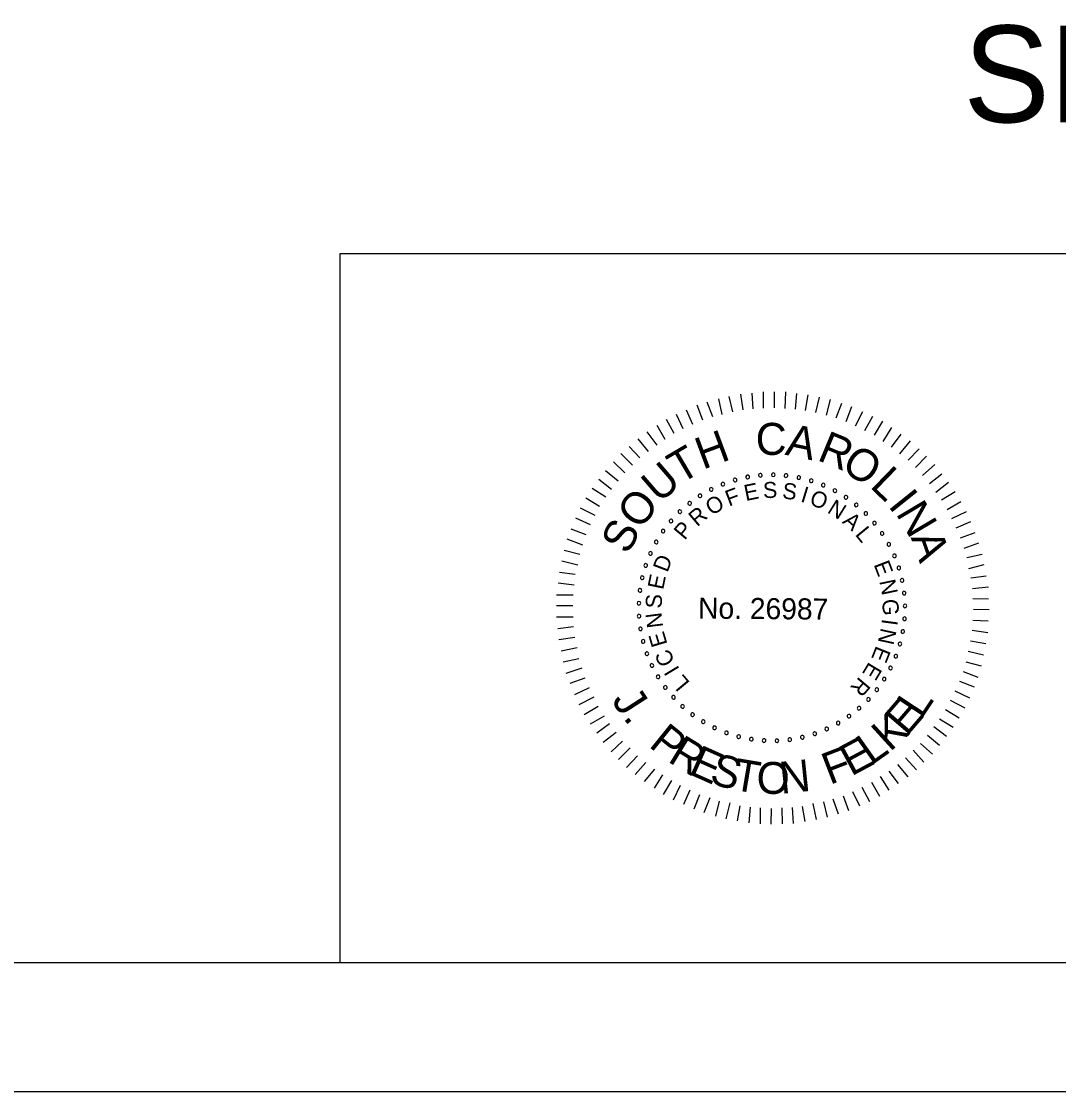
# Model space of a CAD drawing. Extents: x 1970675.2 to 1970711.3, y 796145.2 to 796167.2.
# Drawn here: x 1970696.635 to 1970700.655, y 796145.246 to 796149.396 of the extents above; entities that cross this region are included whole.
import ezdxf

# ---------------------------------------------------------------- set-up
doc = ezdxf.new("R2010")
doc.units = 0
for name, color, linetype in [('BR_BORDER LINES', 7, 'Continuous'), ('BR_TEXT', 7, 'Continuous'), ('Level 31', 7, 'Continuous')]:
    doc.layers.add(name, color=color, linetype=linetype)

msp = doc.modelspace()

# ---------------------------------------------------------------- linework, layer by layer
at = {"layer": 'BR_BORDER LINES'}
for p, q in [((1970697.8703, 796148.4964), (1970703.2355, 796148.4964)), ((1970697.8703, 796145.7463), (1970697.8703, 796148.4964)), ((1970677.0698, 796145.7463), (1970710.7358, 796145.7463))]:
    msp.add_line(p, q, dxfattribs=at)
at = {"layer": 'BR_TEXT'}
for p, q in [((1970699.3925, 796147.882), (1970699.3784, 796147.9414)), ((1970699.432, 796147.8895), (1970699.4231, 796147.9504)), ((1970699.4715, 796147.8934), (1970699.4677, 796147.9544)), ((1970699.511, 796147.8957), (1970699.5116, 796147.96)), ((1970699.5531, 796147.8979), (1970699.5536, 796147.9597)), ((1970699.5951, 796147.895), (1970699.5974, 796147.9593)), ((1970699.6354, 796147.8921), (1970699.6402, 796147.9529)), ((1970699.674, 796147.8875), (1970699.6848, 796147.9483)), ((1970699.7143, 796147.8794), (1970699.7285, 796147.9385)), ((1970699.2755, 796147.8495), (1970699.2545, 796147.9081)), ((1970699.3151, 796147.8621), (1970699.2932, 796147.9198)), ((1970699.3512, 796147.8721), (1970699.338, 796147.9331)), ((1970699.7554, 796147.8688), (1970699.7713, 796147.9295)), ((1970699.7922, 796147.8582), (1970699.8141, 796147.9155)), ((1970699.8316, 796147.8449), (1970699.8535, 796147.9031)), ((1970699.1997, 796147.8158), (1970699.1735, 796147.8718)), ((1970699.2368, 796147.8327), (1970699.2132, 796147.8887)), ((1970699.8675, 796147.8275), (1970699.8954, 796147.883)), ((1970699.9034, 796147.81), (1970699.9347, 796147.8656)), ((1970699.1299, 796147.7744), (1970699.0994, 796147.8287)), ((1970699.1652, 796147.7981), (1970699.1348, 796147.8524)), ((1970699.941, 796147.7917), (1970699.9732, 796147.8455)), ((1970699.9743, 796147.7674), (1970700.0082, 796147.8212)), ((1970699.0651, 796147.7277), (1970699.0252, 796147.7778)), ((1970699.0988, 796147.7532), (1970699.0597, 796147.8041)), ((1970700.0075, 796147.7457), (1970700.044, 796147.796)), ((1970699.0323, 796147.7031), (1970698.9906, 796147.748)), ((1970700.0399, 796147.7197), (1970700.0806, 796147.7691)), ((1970700.0715, 796147.6945), (1970700.1147, 796147.7388)), ((1970698.9735, 796147.6452), (1970698.93, 796147.6876)), ((1970699.0029, 796147.6759), (1970698.9586, 796147.72)), ((1970700.0995, 796147.6668), (1970700.1428, 796147.7102)), ((1970698.9483, 796147.6137), (1970698.8988, 796147.6527)), ((1970700.1276, 796147.6357), (1970700.1752, 796147.6774)), ((1970698.9223, 796147.5804), (1970698.8728, 796147.6203)), ((1970700.1548, 796147.6037), (1970700.2015, 796147.6419)), ((1970700.1786, 796147.57), (1970700.2278, 796147.6091)), ((1970698.9006, 796147.5514), (1970698.8468, 796147.5845)), ((1970700.2006, 796147.5407), (1970700.2532, 796147.5729)), ((1970698.8762, 796147.5147), (1970698.8225, 796147.5469)), ((1970700.2226, 796147.5036), (1970700.2761, 796147.5349)), ((1970698.8588, 796147.4805), (1970698.8024, 796147.5085)), ((1970700.2404, 796147.4691), (1970700.2981, 796147.4961)), ((1970698.8413, 796147.4438), (1970698.7841, 796147.4692)), ((1970700.2581, 796147.4321), (1970700.315, 796147.4565)), ((1970698.8238, 796147.4053), (1970698.7657, 796147.4272)), ((1970700.2749, 796147.3933), (1970700.3318, 796147.4143)), ((1970698.8115, 796147.3651), (1970698.7499, 796147.3879)), ((1970700.2883, 796147.3529), (1970700.346, 796147.3747)), ((1970698.7992, 796147.3291), (1970698.7384, 796147.3442)), ((1970700.2984, 796147.3168), (1970700.3585, 796147.3308)), ((1970698.792, 796147.2871), (1970698.7295, 796147.3031)), ((1970700.3066, 796147.2746), (1970700.3668, 796147.2896)), ((1970698.7814, 796147.2512), (1970698.7205, 796147.2594)), ((1970700.3149, 796147.2385), (1970700.3741, 796147.2458)), ((1970698.7768, 796147.21), (1970698.715, 796147.2174)), ((1970700.3214, 796147.1973), (1970700.3824, 796147.2036)), ((1970698.7738, 796147.1706), (1970698.7095, 796147.1711)), ((1970700.3228, 796147.1578), (1970700.3829, 796147.1573)), ((1970698.7718, 796147.1294), (1970698.7092, 796147.1299)), ((1970700.325, 796147.1166), (1970700.3859, 796147.1161)), ((1970698.7732, 796147.0865), (1970698.7088, 796147.0853)), ((1970700.3221, 796147.0737), (1970700.3822, 796147.0715)), ((1970698.7754, 796147.0478), (1970698.7136, 796147.0406)), ((1970700.32, 796147.0351), (1970700.3809, 796147.0269)), ((1970698.7794, 796147.0066), (1970698.7183, 796146.9977)), ((1970700.3129, 796146.994), (1970700.372, 796146.984)), ((1970698.7893, 796146.9671), (1970698.7266, 796146.9539)), ((1970700.3039, 796146.9546), (1970700.3639, 796146.9403)), ((1970698.7959, 796146.9249), (1970698.7348, 796146.9109)), ((1970700.295, 796146.9126), (1970700.3549, 796146.8975)), ((1970698.8076, 796146.888), (1970698.7456, 796146.867)), ((1970700.2844, 796146.8758), (1970700.3417, 796146.8538)), ((1970698.8192, 796146.8493), (1970698.7607, 796146.8283)), ((1970700.2704, 796146.8373), (1970700.3268, 796146.8153)), ((1970698.8361, 796146.8122), (1970698.7784, 796146.7852)), ((1970698.853, 796146.776), (1970698.7961, 796146.7465)), ((1970700.2529, 796146.8005), (1970700.3093, 796146.7726)), ((1970698.8698, 796146.739), (1970698.8155, 796146.7077)), ((1970700.2346, 796146.7646), (1970700.2918, 796146.7341)), ((1970698.8936, 796146.7019), (1970698.8392, 796146.6706)), ((1970700.1936, 796146.6911), (1970700.2457, 796146.659)), ((1970700.2162, 796146.7279), (1970700.2692, 796146.6957)), ((1970698.9148, 796146.6725), (1970698.8647, 796146.636)), ((1970700.1711, 796146.6622), (1970700.2197, 796146.6248)), ((1970698.9402, 796146.6388), (1970698.8901, 796146.5998)), ((1970700.1468, 796146.6289), (1970700.1928, 796146.589)), ((1970698.9649, 796146.6052), (1970698.9207, 796146.5643)), ((1970698.9938, 796146.5792), (1970698.9488, 796146.5341)), ((1970700.0905, 796146.5701), (1970700.133, 796146.5243)), ((1970700.119, 796146.5956), (1970700.1659, 796146.5541)), ((1970699.0227, 796146.5489), (1970698.9803, 796146.5029)), ((1970700.0619, 796146.5403), (1970700.1044, 796146.4936)), ((1970699.0552, 796146.5229), (1970699.0144, 796146.476)), ((1970699.0884, 796146.4969), (1970699.0485, 796146.4492)), ((1970699.9972, 796146.4894), (1970700.0328, 796146.441)), ((1970700.03, 796146.5149), (1970700.0699, 796146.4673)), ((1970699.1191, 796146.4752), (1970699.0878, 796146.4231)), ((1970699.1541, 796146.4526), (1970699.1228, 796146.3988)), ((1970699.9299, 796146.4462), (1970699.9612, 796146.3918)), ((1970699.9635, 796146.4682), (1970699.9966, 796146.4156)), ((1970699.1883, 796146.4326), (1970699.1612, 796146.377)), ((1970699.225, 796146.4151), (1970699.2005, 796146.3595)), ((1970699.8558, 796146.4099), (1970699.8827, 796146.3539)), ((1970699.8919, 796146.4267), (1970699.9224, 796146.3707)), ((1970699.2635, 796146.3976), (1970699.2416, 796146.3411)), ((1970699.3029, 796146.3853), (1970699.2801, 796146.3271)), ((1970699.3388, 796146.3729), (1970699.3246, 796146.3139)), ((1970699.38, 796146.3658), (1970699.3648, 796146.3041)), ((1970699.7018, 796146.3631), (1970699.715, 796146.3012)), ((1970699.743, 796146.3696), (1970699.758, 796146.3103)), ((1970699.78, 796146.3813), (1970699.801, 796146.3228)), ((1970699.8196, 796146.393), (1970699.8406, 796146.3362)), ((1970699.4193, 796146.3543), (1970699.4094, 796146.296)), ((1970699.4588, 796146.3497), (1970699.454, 796146.2879)), ((1970699.4982, 796146.3468), (1970699.4977, 796146.285)), ((1970699.5402, 796146.3438), (1970699.5397, 796146.2829)), ((1970699.5823, 796146.3461), (1970699.5835, 796146.2842)), ((1970699.6227, 796146.3483), (1970699.6264, 796146.2865)), ((1970699.6613, 796146.3523), (1970699.6712, 796146.2938))]:
    msp.add_line(p, q, dxfattribs=at)
for centre, start, end in [((1970699.3539, 796147.6019), 21.6807, 201.6807), ((1970699.3539, 796147.6019), 201.6807, 21.6807), ((1970699.4011, 796147.6179), 16.1422, 196.1422), ((1970699.4011, 796147.6179), 196.1422, 16.1422), ((1970699.4496, 796147.6294), 10.6038, 190.6038), ((1970699.4496, 796147.6294), 190.6038, 10.6038), ((1970699.499, 796147.6361), 5.0653, 185.0653), ((1970699.499, 796147.6361), 185.0653, 5.0653), ((1970699.5488, 796147.638), 359.5268, 179.5268), ((1970699.5488, 796147.638), 179.5268, 359.5268), ((1970699.5985, 796147.635), 173.9884, 353.9884), ((1970699.5985, 796147.635), 353.9884, 173.9884), ((1970699.6478, 796147.6273), 168.4499, 348.4499), ((1970699.6478, 796147.6273), 348.4499, 168.4499), ((1970699.696, 796147.6149), 162.9114, 342.9114), ((1970699.696, 796147.6149), 342.9114, 162.9114), ((1970699.7429, 796147.5979), 337.373, 157.373), ((1970699.2653, 796147.5565), 32.7576, 212.7576), ((1970699.3085, 796147.5813), 27.2191, 207.2191), ((1970699.3085, 796147.5813), 207.2191, 27.2191), ((1970699.7429, 796147.5979), 157.373, 337.373), ((1970699.7878, 796147.5764), 151.8345, 331.8345), ((1970699.7878, 796147.5764), 331.8345, 151.8345), ((1970699.2247, 796147.5276), 38.2961, 218.2961), ((1970699.2247, 796147.5276), 218.2961, 38.2961), ((1970699.2653, 796147.5565), 212.7576, 32.7576), ((1970699.8305, 796147.5507), 146.2961, 326.2961), ((1970699.8305, 796147.5507), 326.2961, 146.2961), ((1970699.8705, 796147.521), 140.7576, 320.7576), ((1970699.8705, 796147.521), 320.7576, 140.7576), ((1970699.1871, 796147.495), 43.8345, 223.8345), ((1970699.1871, 796147.495), 223.8345, 43.8345), ((1970699.9075, 796147.4876), 135.2191, 315.2191), ((1970699.9075, 796147.4876), 315.2191, 135.2191), ((1970699.1528, 796147.4588), 49.373, 229.373), ((1970699.1528, 796147.4588), 229.373, 49.373), ((1970699.9411, 796147.4508), 129.6807, 309.6807), ((1970699.9411, 796147.4508), 309.6807, 129.6807), ((1970699.1221, 796147.4196), 54.9114, 234.9114), ((1970699.1221, 796147.4196), 234.9114, 54.9114), ((1970699.9709, 796147.4109), 124.1422, 304.1422), ((1970699.9709, 796147.4109), 304.1422, 124.1422), ((1970699.0954, 796147.3775), 60.4499, 240.4499), ((1970699.0954, 796147.3775), 240.4499, 60.4499), ((1970699.9968, 796147.3683), 118.6038, 298.6038), ((1970699.9968, 796147.3683), 298.6038, 118.6038), ((1970699.0729, 796147.3331), 65.9884, 245.9884), ((1970699.0729, 796147.3331), 245.9884, 65.9884), ((1970700.0184, 796147.3234), 113.0653, 293.0653), ((1970700.0184, 796147.3234), 293.0653, 113.0653), ((1970699.0547, 796147.2867), 71.5268, 251.5268), ((1970699.0547, 796147.2867), 251.5268, 71.5268), ((1970700.0356, 796147.2766), 107.5268, 287.5268), ((1970700.0356, 796147.2766), 287.5268, 107.5268), ((1970699.0411, 796147.2387), 77.0653, 257.0653), ((1970699.0411, 796147.2387), 257.0653, 77.0653), ((1970700.0482, 796147.2284), 101.9884, 281.9884), ((1970700.0482, 796147.2284), 281.9884, 101.9884), ((1970699.0322, 796147.1897), 82.6038, 262.6038), ((1970699.0322, 796147.1897), 262.6038, 82.6038), ((1970700.0561, 796147.1792), 96.4499, 276.4499), ((1970700.0561, 796147.1792), 276.4499, 96.4499), ((1970699.0281, 796147.14), 88.1422, 268.1422), ((1970699.0281, 796147.14), 268.1422, 88.1422), ((1970700.0592, 796147.1295), 90.9114, 270.9114), ((1970700.0592, 796147.1295), 270.9114, 90.9114), ((1970699.0288, 796147.0902), 93.6807, 273.6807), ((1970699.0288, 796147.0902), 273.6807, 93.6807), ((1970700.0575, 796147.0797), 85.373, 265.373), ((1970700.0575, 796147.0797), 265.373, 85.373), ((1970699.0343, 796147.0407), 99.2191, 279.2191), ((1970699.0343, 796147.0407), 279.2191, 99.2191), ((1970700.0509, 796147.0303), 79.8345, 259.8345), ((1970700.0509, 796147.0303), 259.8345, 79.8345), ((1970699.0446, 796146.9919), 104.7576, 284.7576), ((1970699.0446, 796146.9919), 284.7576, 104.7576), ((1970700.0397, 796146.9817), 74.2961, 254.2961), ((1970700.0397, 796146.9817), 254.2961, 74.2961), ((1970699.0595, 796146.9444), 110.2961, 290.2961), ((1970699.0595, 796146.9444), 290.2961, 110.2961), ((1970700.0238, 796146.9345), 68.7576, 248.7576), ((1970700.0238, 796146.9345), 248.7576, 68.7576), ((1970699.0789, 796146.8985), 115.8345, 295.8345), ((1970699.0789, 796146.8985), 295.8345, 115.8345), ((1970699.1027, 796146.8547), 121.373, 301.373), ((1970699.1027, 796146.8547), 301.373, 121.373), ((1970700.0034, 796146.889), 63.2191, 243.2191), ((1970700.0034, 796146.889), 243.2191, 63.2191), ((1970699.1306, 796146.8134), 126.9114, 306.9114), ((1970699.1306, 796146.8134), 306.9114, 126.9114), ((1970699.9788, 796146.8457), 57.6807, 237.6807), ((1970699.9788, 796146.8457), 237.6807, 57.6807), ((1970699.1623, 796146.775), 132.4499, 312.4499), ((1970699.1623, 796146.775), 312.4499, 132.4499), ((1970699.9175, 796146.7672), 46.6038, 226.6038), ((1970699.9501, 796146.805), 52.1422, 232.1422), ((1970699.9501, 796146.805), 232.1422, 52.1422), ((1970699.1976, 796146.7398), 137.9884, 317.9884), ((1970699.1976, 796146.7398), 317.9884, 137.9884), ((1970699.8815, 796146.7328), 41.0653, 221.0653), ((1970699.8815, 796146.7328), 221.0653, 41.0653), ((1970699.9175, 796146.7672), 226.6038, 46.6038), ((1970699.2361, 796146.7082), 143.5268, 323.5268), ((1970699.2361, 796146.7082), 323.5268, 143.5268), ((1970699.8423, 796146.702), 35.5268, 215.5268), ((1970699.8423, 796146.702), 215.5268, 35.5268), ((1970699.2775, 796146.6805), 149.0653, 329.0653), ((1970699.2775, 796146.6805), 329.0653, 149.0653), ((1970699.3214, 796146.6569), 154.6038, 334.6038), ((1970699.3214, 796146.6569), 334.6038, 154.6038), ((1970699.756, 796146.6524), 24.4499, 204.4499), ((1970699.756, 796146.6524), 204.4499, 24.4499), ((1970699.8004, 796146.6751), 29.9884, 209.9884), ((1970699.8004, 796146.6751), 209.9884, 29.9884), ((1970699.3674, 796146.6376), 160.1422, 340.1422), ((1970699.3674, 796146.6376), 340.1422, 160.1422), ((1970699.415, 796146.6229), 165.6807, 345.6807), ((1970699.415, 796146.6229), 345.6807, 165.6807), ((1970699.4638, 796146.6128), 351.2191, 171.2191), ((1970699.4638, 796146.6128), 171.2191, 351.2191), ((1970699.5133, 796146.6075), 356.7576, 176.7576), ((1970699.5133, 796146.6075), 176.7576, 356.7576), ((1970699.5632, 796146.607), 2.2961, 182.2961), ((1970699.6128, 796146.6113), 7.8345, 187.8345), ((1970699.6128, 796146.6113), 187.8345, 7.8345), ((1970699.6618, 796146.6203), 13.373, 193.373), ((1970699.6618, 796146.6203), 193.373, 13.373), ((1970699.7097, 796146.6341), 18.9114, 198.9114), ((1970699.7097, 796146.6341), 198.9114, 18.9114), ((1970699.5632, 796146.607), 182.2961, 2.2961)]:
    msp.add_arc(centre, 0.00701, start, end, dxfattribs=at)
at = {"layer": 'Level 31'}
msp.add_lwpolyline([(1970675.2365, 796145.2464), (1970711.2364, 796145.2464), (1970711.2364, 796167.2463), (1970675.2365, 796167.2463)], close=True, dxfattribs=at)

# ---------------------------------------------------------------- texts
at = {"layer": 'BR_TEXT'}
for s, height, rotation, p in [('SECTION C-C', 0.375005, 360, (1970700.286, 796149.0049)), ('C', 0.1241, 359.5482, (1970699.4803, 796147.7155)), ('A', 0.1241, 348.1981, (1970699.5917, 796147.7163)), ('H', 0.1241, 20.3637, (1970699.2759, 796147.6572)), ('R', 0.1241, 337.4344, (1970699.715, 796147.6965)), ('T', 0.1241, 30.4992, (1970699.188, 796147.5997)), ('O', 0.1239, 326.5869, (1970699.8072, 796147.6597)), ('U', 0.1241, 40.8022, (1970699.1068, 796147.525)), ('L', 0.1241, 315.9488, (1970699.9198, 796147.5919)), ('E', 0.0622, 11.4103, (1970699.4423, 796147.536)), ('S', 0.0622, 2.208, (1970699.5102, 796147.547)), ('S', 0.0622, 352.6608, (1970699.5814, 796147.5468)), ('O', 0.1241, 52.0267, (1970699.0323, 796147.421)), ('F', 0.0622, 20.6127, (1970699.3772, 796147.5143)), ('I', 0.0622, 343.1136, (1970699.6517, 796147.5348)), ('O', 0.0622, 338.4392, (1970699.6851, 796147.5247)), ('I', 0.1241, 308.6613, (1970699.9912, 796147.5176)), ('O', 0.0622, 30.8477, (1970699.3098, 796147.4783)), ('N', 0.0622, 328.2042, (1970699.7547, 796147.4933)), ('N', 0.1241, 300.7037, (1970700.0218, 796147.4883)), ('R', 0.0622, 40.3949, (1970699.2537, 796147.4344)), ('A', 0.0622, 318.657, (1970699.8137, 796147.4532)), ('S', 0.1239, 63.2511, (1970698.9869, 796147.3254)), ('P', 0.0622, 49.9421, (1970699.2056, 796147.3818)), ('L', 0.0622, 309.4546, (1970699.8635, 796147.4059)), ('A', 0.1241, 289.4792, (1970700.081, 796147.3952)), ('D', 0.0622, 69.0364, (1970699.1386, 796147.2566)), ('E', 0.0622, 291.049, (1970699.9373, 796147.2906)), ('E', 0.0622, 78.2388, (1970699.122, 796147.1899)), ('N', 0.0622, 281.8466, (1970699.9595, 796147.2256)), ('S', 0.0622, 87.786, (1970699.1163, 796147.1189)), ('No. 26987', 0.08175, 359.5268, (1970699.2574, 796147.0804)), ('G', 0.0622, 272.2995, (1970699.9713, 796147.1553)), ('N', 0.0622, 97.3332, (1970699.1225, 796147.0479)), ('I', 0.0622, 262.4084, (1970699.9709, 796147.0814)), ('E', 0.0622, 106.5355, (1970699.1395, 796146.9813)), ('N', 0.0622, 257.7339, (1970699.9664, 796147.0468)), ('C', 0.0622, 116.4266, (1970699.1694, 796146.9138)), ('E', 0.0622, 248.1867, (1970699.9483, 796146.9779)), ('E', 0.0622, 238.9844, (1970699.9204, 796146.9151)), ('I', 0.0622, 121.1011, (1970699.1875, 796146.8839)), ('L', 0.0622, 129.9595, (1970699.2281, 796146.8318)), ('R', 0.0622, 229.782, (1970699.8827, 796146.8577)), ('J', 0.1236, 302.9559, (1970698.9202, 796146.7633)), ('E', 0.1236, 49.3639, (1970700.0662, 796146.6214)), ('L', 0.1236, 56.4247, (1970700.1237, 796146.6891)), ('.', 0.1236, 309.3974, (1970698.9643, 796146.6953)), ('K', 0.1236, 42.3031, (1970700.0009, 796146.5613)), ('P', 0.1236, 321.1035, (1970699.0627, 796146.5861)), ('R', 0.1236, 328.5359, (1970699.136, 796146.528)), ('E', 0.1236, 28.1814, (1970699.8506, 796146.4673)), ('L', 0.1236, 35.2422, (1970699.9286, 796146.5097)), ('E', 0.1236, 335.9684, (1970699.2161, 796146.4799)), ('F', 0.1236, 21.1206, (1970699.7679, 796146.4348)), ('S', 0.1236, 343.0292, (1970699.2974, 796146.4442)), ('T', 0.1236, 350.4617, (1970699.3871, 796146.4177)), ('O', 0.1236, 358.1419, (1970699.4825, 796146.4028)), ('N', 0.1236, 5.8221, (1970699.579, 796146.4007))]:
    msp.add_text(s, height=height, rotation=rotation, dxfattribs=at).set_placement(p)

doc.saveas('drawing.dxf')
